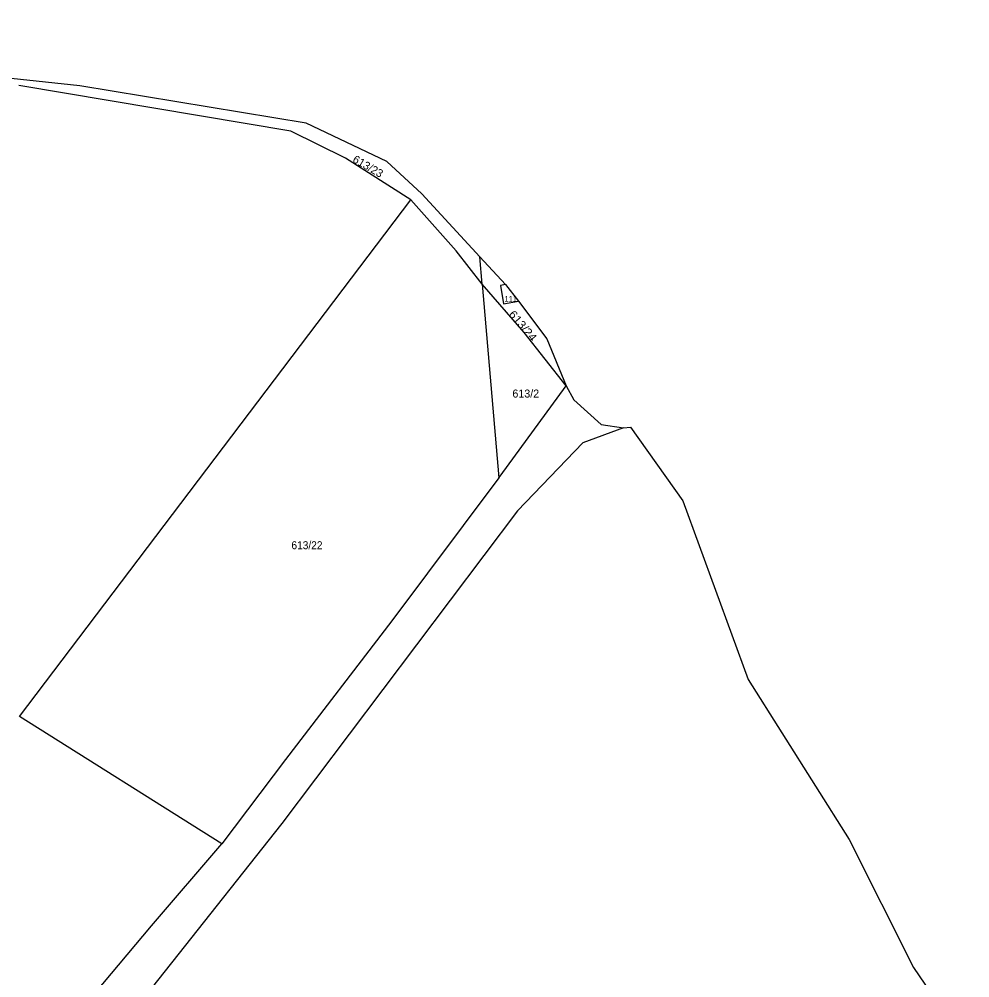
# Model space of a CAD drawing. Extents: x -687135 to -684370, y -1007309 to -1005782.
# Drawn here: x -684594.1 to -684392, y -1006317.9 to -1006114.2 of the extents above; entities that cross this region are included whole.
import ezdxf

# ---------------------------------------------------------------- set-up
doc = ezdxf.new("R2010")
doc.units = 0
doc.header["$LTSCALE"] = 0.68
doc.layers.add('1', color=7, linetype='Continuous', lineweight=25)
doc.layers.add('2', color=7, linetype='Continuous')

msp = doc.modelspace()

# ---------------------------------------------------------------- linework, layer by layer
at = {"layer": '1'}
for p, q in [((-684496.16, -1006164.73), (-684490.73, -1006170.61)), ((-684495.66, -1006170.54), (-684496.16, -1006164.73)), ((-684490.73, -1006170.61), (-684487.95, -1006174.14)), ((-684487.95, -1006174.14), (-684481.96, -1006182.18)), ((-684481.96, -1006182.18), (-684477.86, -1006192.17))]:
    msp.add_line(p, q, dxfattribs=at)
for points in [[(-684533.09, -1006136.3), (-684581.21, -1006128.36), (-684648.95, -1006121.18), (-684680.43, -1006118), (-684688.19, -1006114.23)], [(-684510.85, -1006152.6), (-684524.72, -1006143.73), (-684536.34, -1006138), (-684594.2, -1006128.33)], [(-684496.16, -1006164.73), (-684508.5, -1006151.36), (-684515.93, -1006144.5), (-684533.09, -1006136.3)], [(-684551.05, -1006289.44), (-684594.05, -1006262.43), (-684510.85, -1006152.6)], [(-684495.66, -1006170.54), (-684501.25, -1006163.43), (-684510.85, -1006152.6)], [(-684477.86, -1006192.17), (-684486.75, -1006180.8), (-684495.66, -1006170.54), (-684492.15, -1006211.69)], [(-684490.73, -1006170.61), (-684491.82, -1006170.8), (-684491.15, -1006174.69), (-684487.95, -1006174.14)], [(-684492.15, -1006211.69), (-684491.89, -1006211.35), (-684477.86, -1006192.17)], [(-684477.86, -1006192.17), (-684476.22, -1006195.12), (-684470.38, -1006200.39), (-684465.61, -1006201.09), (-684464.16, -1006200.93)], [(-684465.61, -1006201.09), (-684474.26, -1006204.25), (-684488.16, -1006218.72), (-684538.26, -1006285.17), (-684585.17, -1006344.33), (-684651.09, -1006431.43), (-684663.47, -1006466.37), (-684672.76, -1006511.35), (-684682.63, -1006539.99), (-684683.56, -1006543.2)], [(-684464.16, -1006200.93), (-684453.04, -1006216.6), (-684439.17, -1006254.53), (-684417.7, -1006288.55), (-684404.01, -1006315.71), (-684394.08, -1006330.36), (-684392.01, -1006333.79)], [(-684492.15, -1006211.69), (-684514.88, -1006242.08), (-684537.49, -1006271.51), (-684551.05, -1006289.44)], [(-684588.56, -1006333.7), (-684566.02, -1006306.89), (-684551.05, -1006289.44)]]:
    msp.add_lwpolyline(points, dxfattribs=at)

# ---------------------------------------------------------------- texts
at = {"layer": '2'}
msp.add_text('613/23', height=1.7, rotation=330, dxfattribs=at).set_placement((-684523.395, -1006144.496))
for s, height, p in [('111', 1.19, (-684490.94, -1006174.255)), ('613/2', 1.7, (-684489.26, -1006194.63))]:
    msp.add_text(s, height=height, dxfattribs=at).set_placement(p)
at = {"layer": '2', "width": 1.1}
msp.add_text('613/24', height=1.7, rotation=310, dxfattribs=at).set_placement((-684490.141, -1006177.006))
at = {"layer": '2', "width": 0.95}
msp.add_text('613/22', height=1.7, dxfattribs=at).set_placement((-684536.24, -1006226.86))

doc.saveas('drawing.dxf')
